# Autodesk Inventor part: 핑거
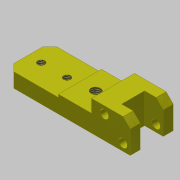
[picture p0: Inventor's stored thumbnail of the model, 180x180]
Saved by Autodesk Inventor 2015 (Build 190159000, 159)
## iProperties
Created: 2019-02
Part Number: 핑거
Material: 알루미늄 6061
Document SubType Name: Modeling
Designer: mduedu
Density: 1 g/cm^3
Appearance: 노란색
Author: mduedu
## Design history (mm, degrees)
sketch "스케치1"
  geometry: L1 (0, 0)-(-86, 0); L2 (-86, 0)-(-86, 21); L3 (-86, 21)-(0, 21); L4 (0, 21)-(0, 0)
  constraints: 8 end point, 2 parallel, 1 horizontal, 1 perpendicular
  dimensions: "d0" = 86 distance of L2.end L3.end; "d1" = 21 distance of L1.end L2.end
extrude "돌출1" new body sketch "스케치1" stored distance "d2" = 30; taper "d3" = 0 deg
sketch "스케치2"
  geometry: L1 (-86, 0)-(0, 0) reference; L2 (0, 0)-(0, 21) reference; L3 (0, 21)-(-86, 21) reference; L4 (-86, 21)-(-86, 0) reference; L5 (-86, 10)-(-50, 10); L6 (-50, 10)-(-50, 21); L7 (-50, 21)-(-86, 21); L8 (-86, 21)-(-86, 10); L9 (-50, 12)-(-27, 12); L10 (-27, 12)-(-27, 21); L11 (-27, 21)-(-50, 21); L12 (-50, 21)-(-50, 12); 1 further point
  constraints: 16 end point, 4 parallel, 4 point on line, 2 horizontal, 2 perpendicular
  dimensions: "d4" = 27 distance between parallel lines of L10 L2; "d5" = 12 distance between parallel lines of L1 L9; "d6" = 36 distance between parallel lines of L6 L4; "d7" = 10 distance between parallel lines of L1 L5
extrude "돌출2" cut sketch "스케치2" stored distance "d8" = 30; taper "d9" = 0 deg
chamfer "모따기1" distance "d10" = 5; stored, may be unused: second distance "d11" = 2, angle "d12" = 45 deg
sketch "스케치3"
  geometry: L1 (27, 0)-(27, 30) reference; L2 (27, 23)-(14, 23); L3 (14, 23)-(14, 7); L4 (14, 7)-(27, 7); L5 (27, 7)-(27, 23); 2 further points
  constraints: 8 end point, 2 midpoint, 2 parallel, 1 horizontal, 1 perpendicular, 1 point on line
  dimensions: "d13" = 16 distance between parallel lines of L4 L2; "d15" = 13 distance of L2.start L2.end
extrude "돌출3" cut sketch "스케치3" stored distance "d16" = 30; taper "d17" = 0 deg
sketch "스케치4"
  geometry: 3 further points
  dimensions: "d18" = 5 horizontal distance of point (-5, 5) point (0, 0); "d19" = 5 horizontal distance of point (-5, 5) point (0, 0); "d20" = 11 vertical distance of point (-18, 16) point (-5, 5); "d21" = 13 horizontal distance of point (-18, 16) point (-5, 5)
hole "구멍1" sketch "스케치4" at (-5, 5), (-18, 16) diameter "d22" = 6; stored, may be unused: countersink angle "d26" = 90 deg, drill point angle "d28" = 118 deg; dims "d23" = 6, "d24" = 4, "d25" = 2, "d27" = 8
sketch "스케치5"
  geometry: L1 (0, 0)-(0, 30) reference; 3 further points
  constraints: 2 horizontal alignment
  dimensions: "d29" = 9 distance from line of point (9, 15) L1; "d30" = 18 distance of point (27, 15) point (9, 15)
hole "구멍2" sketch "스케치5" diameter "d31" = 4.917; stored, may be unused: countersink angle "d35" = 90 deg, drill point angle "d37" = 118 deg; dims "d32" = 6, "d33" = 4, "d34" = 2, "d36" = 8
sketch "스케치6"
  geometry: 3 further points
  constraints: 1 horizontal alignment
  dimensions: "d38" = 20 distance of point (11, 15) point (-9, 15)
hole "구멍3" sketch "스케치6" at (11, 15) diameter "d39" = 6.647; stored, may be unused: countersink angle "d43" = 90 deg, drill point angle "d45" = 118 deg; dims "d40" = 6, "d41" = 4, "d42" = 2, "d44" = 8
chamfer "모따기2" distance "d46" = 5; stored, may be unused: second distance "d47" = 2, angle "d48" = 45 deg
node "솔리드1"
node "투영된 루프1"
